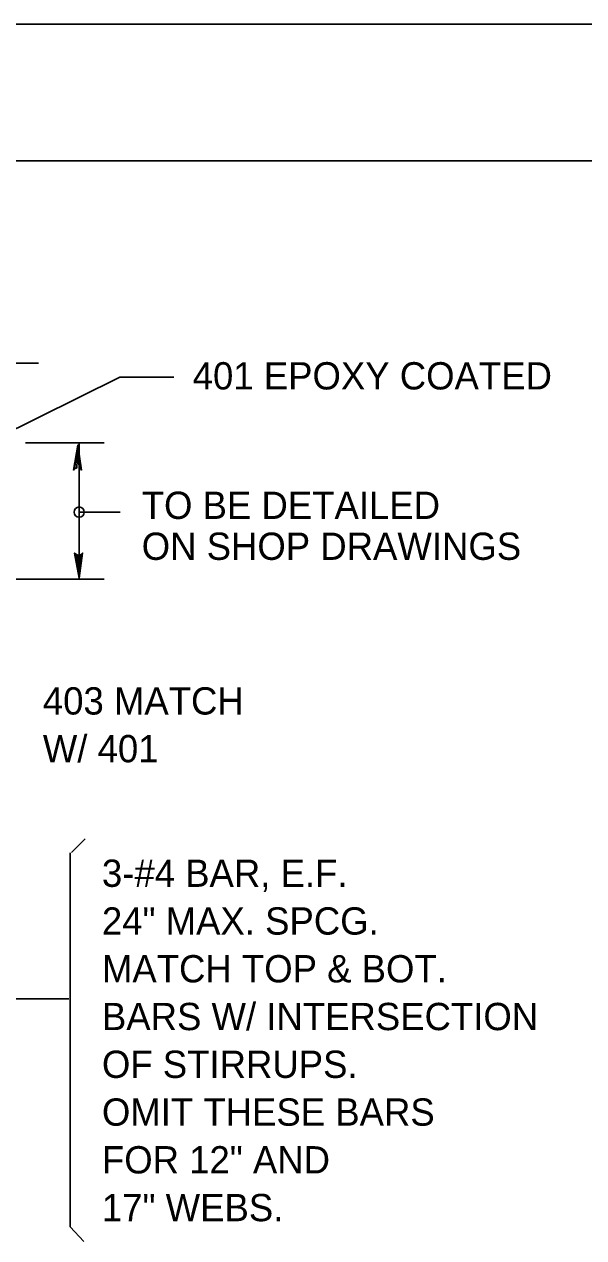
# Model space of a CAD drawing. Extents: x 637933 to 640019, y 298854 to 300042.
# Drawn here: x 638585.2 to 638646.7, y 299908.7 to 300042.1 of the extents above; entities that cross this region are included whole.
import ezdxf

# ---------------------------------------------------------------- set-up
doc = ezdxf.new("R2010")
doc.units = 0
doc.layers.add('1', color=7, linetype='Continuous')
doc.layers.add('PLT-BNDY', color=7, linetype='Continuous')

msp = doc.modelspace()

# ---------------------------------------------------------------- linework, layer by layer
at = {"layer": '1'}
for p, q in [((638023.93, 300027.12), (638809.94, 300027.12)), ((638586.76, 300004.87), (638504.33, 300004.87)), ((638595.7, 300003.34), (638567.08, 299989.12)), ((638595.7, 300003.34), (638601.63, 300003.34)), ((638593.99, 299996.12), (638585.35, 299996.12)), ((638591.24, 299981.12), (638591.24, 299996)), ((638591.24, 299988.5), (638595.74, 299988.5)), ((638593.99, 299981.12), (638577.24, 299981.12)), ((638591.88, 299952.58), (638590.38, 299951.08)), ((638590.24, 299909.96), (638590.24, 299951.04)), ((638582.86, 299935), (638590.11, 299935)), ((638590.24, 299909.96), (638591.74, 299908.34))]:
    msp.add_line(p, q, dxfattribs=at)
for points in [[(638590.74, 299993.25), (638590.99, 299993.37), (638591.11, 299995.87), (638590.74, 299993.25), (638590.61, 299993.12), (638591.11, 299995.87), (638591.24, 299993.37), (638591.36, 299993.37), (638591.11, 299995.87), (638591.49, 299993.12), (638591.36, 299993.37)], [(638591.49, 299983.87), (638591.36, 299983.75), (638591.24, 299981.25), (638591.49, 299983.87), (638591.61, 299984), (638591.24, 299981.25), (638591.11, 299983.75), (638590.86, 299983.87), (638591.24, 299981.25), (638590.74, 299984), (638590.86, 299983.87)]]:
    msp.add_lwpolyline(points, dxfattribs=at)
msp.add_circle((638591.24, 299988.5), 0.563, dxfattribs=at)
at = {"layer": 'PLT-BNDY'}
msp.add_lwpolyline([(637983.93, 300042.12), (638824.93, 300042.12), (638824.93, 299448.12), (637983.93, 299448.12)], close=True, dxfattribs=at)

# ---------------------------------------------------------------- texts
at = {"layer": '1'}
for s, p in [('401 EPOXY COATED', (638603.71, 300001.98)), ('TO BE DETAILED', (638598.11, 299987.75)), ('ON SHOP DRAWINGS', (638598.11, 299983.25)), ('403 MATCH', (638587.25, 299966.25)), ('W/ 401', (638587.25, 299961)), ('3-#4 BAR, E.F.', (638593.74, 299947.31)), ('24" MAX. SPCG.', (638593.74, 299942.06)), ('MATCH TOP & BOT. ', (638593.74, 299936.81)), ('BARS W/ INTERSECTION', (638593.74, 299931.56)), ('OF STIRRUPS.', (638593.74, 299926.31)), ('OMIT THESE BARS', (638593.74, 299921.06)), ('FOR 12" AND', (638593.74, 299915.81)), ('17" WEBS.', (638593.74, 299910.56))]:
    msp.add_text(s, height=3, dxfattribs=at).set_placement(p)

doc.saveas('drawing.dxf')
